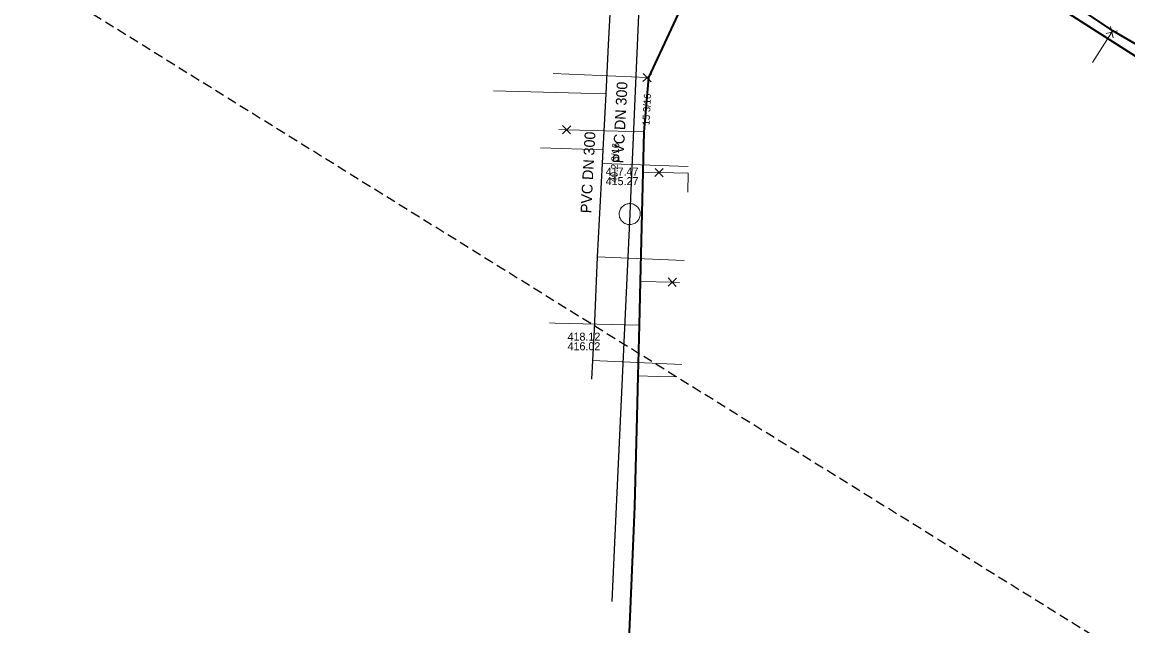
# Model space of a CAD drawing. Extents: x -772952 to -772403, y -1033777 to -1033210.
# Drawn here: x -772951.7 to -772827.4, y -1033657.9 to -1033589.9 of the extents above; entities that cross this region are included whole.
import ezdxf

# ---------------------------------------------------------------- set-up
doc = ezdxf.new("R2010")
doc.units = 0
doc.header["$LTSCALE"] = 0.36
doc.linetypes.add('MEDIUM_DASHED', pattern=[4.5, 3, -1.5])
for name, color, linetype, lineweight in [('15', 7, 'Continuous', 13), ('16', 7, 'Continuous', 35), ('2', 7, 'Continuous', 25), ('4', 7, 'Continuous', 13), ('57', 7, 'Continuous', 13), ('59', 7, 'Continuous', 13), ('62', 7, 'MEDIUM_DASHED', 25)]:
    doc.layers.add(name, color=color, linetype=linetype, lineweight=lineweight)
doc.layers.add('3', color=7, linetype='Continuous')
doc.layers.add('6', color=7, linetype='Continuous')

msp = doc.modelspace()

# ---------------------------------------------------------------- linework, layer by layer
at = {"layer": '15'}
for p, q in [((-772829.321, -1033590.429), (-772829.041, -1033591.701)), ((-772828.553, -1033590.926), (-772829.814, -1033591.2)), ((-772880.951, -1033595.741), (-772881.912, -1033596.62)), ((-772880.997, -1033596.655), (-772881.865, -1033595.701)), ((-772890.015, -1033601.595), (-772890.958, -1033602.492)), ((-772890.042, -1033602.509), (-772890.93, -1033601.573)), ((-772880.561, -1033607.307), (-772879.616, -1033606.41)), ((-772880.532, -1033606.392), (-772879.646, -1033607.33)), ((-772879.078, -1033619.639), (-772878.135, -1033618.742)), ((-772879.051, -1033618.724), (-772878.164, -1033619.662))]:
    msp.add_line(p, q, dxfattribs=at)
at = {"layer": '16'}
for points in [[(-772759.272, -1033597.956), (-772777.938, -1033599.996), (-772804.013, -1033600.436), (-772815.616, -1033598.743), (-772829.081, -1033590.92), (-772839.554, -1033583.848), (-772854.907, -1033577.034), (-772868.037, -1033573.403), (-772870.403, -1033572.723)], [(-772888.497, -1033769.491), (-772888.037, -1033763.55), (-772887.271, -1033741.784), (-772886.864, -1033730.232), (-772886.524, -1033720.537), (-772886.265, -1033713.186), (-772886.123, -1033710.892), (-772885.144, -1033695.171), (-772884.647, -1033687.179), (-772883.979, -1033671.67), (-772883.189, -1033653.357), (-772882.844, -1033645.361), (-772882.811, -1033644.388), (-772882.563, -1033634.359), (-772882.448, -1033629.743), (-772882.307, -1033624.035), (-772882.184, -1033619.103), (-772881.88, -1033606.815), (-772881.767, -1033602.26), (-772881.241, -1033596.171), (-772876.388, -1033585.752), (-772873.983, -1033580.212), (-772872.449, -1033576.679), (-772871.839, -1033575.434)], [(-772871.839, -1033575.434), (-772870.427, -1033576.155), (-772849.008, -1033581.096), (-772841.55, -1033584.107), (-772822.87, -1033596.07), (-772815.517, -1033599.879), (-772800.324, -1033602.374), (-772785.625, -1033603.857), (-772759.69, -1033599.467), (-772726.1, -1033595.877), (-772705.133, -1033594.197), (-772687.467, -1033594.611), (-772649.087, -1033602.85)]]:
    msp.add_lwpolyline(points, dxfattribs=at)
at = {"layer": '2'}
for points in [[(-772885.23, -1033580.92), (-772885.425, -1033584.844), (-772885.564, -1033587.637), (-772885.806, -1033592.497), (-772886.08, -1033597.99), (-772886.395, -1033604.32), (-772886.471, -1033605.845), (-772887.037, -1033616.344), (-772887.401, -1033624.519), (-772887.574, -1033627.991), (-772887.68, -1033630.11)], [(-772882.37, -1033588.25), (-772883.311, -1033609.744), (-772883.39, -1033611.53)], [(-772883.39, -1033611.53), (-772884.21, -1033629.155), (-772885.148, -1033649.309), (-772885.42, -1033655.13)]]:
    msp.add_lwpolyline(points, dxfattribs=at)
at = {"layer": '4'}
msp.add_lwpolyline([(-772882.21, -1033611.53), (-772882.216, -1033611.411), (-772882.234, -1033611.294), (-772882.263, -1033611.178), (-772882.304, -1033611.067), (-772882.356, -1033610.96), (-772882.419, -1033610.859), (-772882.492, -1033610.764), (-772882.573, -1033610.678), (-772882.663, -1033610.6), (-772882.761, -1033610.531), (-772882.864, -1033610.473), (-772882.973, -1033610.426), (-772883.087, -1033610.389), (-772883.203, -1033610.364), (-772883.321, -1033610.352), (-772883.44, -1033610.351), (-772883.559, -1033610.362), (-772883.675, -1033610.385), (-772883.789, -1033610.419), (-772883.899, -1033610.465), (-772884.004, -1033610.522), (-772884.102, -1033610.589), (-772884.193, -1033610.665), (-772884.276, -1033610.75), (-772884.35, -1033610.844), (-772884.414, -1033610.944), (-772884.468, -1033611.05), (-772884.511, -1033611.161), (-772884.543, -1033611.275), (-772884.562, -1033611.393), (-772884.57, -1033611.512), (-772884.566, -1033611.63), (-772884.55, -1033611.748), (-772884.522, -1033611.864), (-772884.483, -1033611.976), (-772884.432, -1033612.084), (-772884.371, -1033612.186), (-772884.3, -1033612.282), (-772884.22, -1033612.369), (-772884.131, -1033612.449), (-772884.035, -1033612.519), (-772883.932, -1033612.579), (-772883.824, -1033612.628), (-772883.711, -1033612.666), (-772883.595, -1033612.692), (-772883.477, -1033612.707), (-772883.358, -1033612.71), (-772883.24, -1033612.701), (-772883.122, -1033612.68), (-772883.008, -1033612.647), (-772882.898, -1033612.603), (-772882.792, -1033612.548), (-772882.693, -1033612.482), (-772882.6, -1033612.407), (-772882.516, -1033612.323), (-772882.441, -1033612.231), (-772882.375, -1033612.132), (-772882.319, -1033612.027), (-772882.275, -1033611.917), (-772882.241, -1033611.803), (-772882.22, -1033611.686), (-772882.21, -1033611.567)], close=True, dxfattribs=at)
at = {"layer": '57'}
for p, q in [((-772886.08, -1033597.99), (-772898.72, -1033597.66)), ((-772886.395, -1033604.32), (-772893.44, -1033604.07)), ((-772886.471, -1033605.845), (-772876.83, -1033606.18)), ((-772887.037, -1033616.344), (-772877.25, -1033616.75)), ((-772887.574, -1033627.991), (-772877.53, -1033628.44))]:
    msp.add_line(p, q, dxfattribs=at)
at = {"layer": '59'}
for points in [[(-772829.082, -1033590.92), (-772829.182, -1033591.064), (-772831.35, -1033594.459)], [(-772881.241, -1033596.172), (-772881.431, -1033596.18), (-772891.987, -1033595.71)], [(-772881.767, -1033602.259), (-772890.486, -1033602.044), (-772891.347, -1033602.023)], [(-772881.88, -1033606.815), (-772880.09, -1033606.86), (-772876.813, -1033606.944), (-772876.84, -1033609.074)], [(-772882.185, -1033619.104), (-772878.608, -1033619.192), (-772877.797, -1033619.213)], [(-772882.307, -1033624.035), (-772891.781, -1033623.8), (-772892.394, -1033623.785)], [(-772882.448, -1033629.744), (-772880.312, -1033629.797), (-772878.097, -1033629.852)]]:
    msp.add_lwpolyline(points, dxfattribs=at)
at = {"layer": '62'}
msp.add_lwpolyline([(-772641.514, -1033776.98), (-772641.529, -1033776.987), (-772951.708, -1033584.106), (-772846.395, -1033249.938), (-772562.451, -1033323.146)], close=True, dxfattribs=at)

# ---------------------------------------------------------------- texts
at = {"layer": '3'}
for s, height, p in [('PVC DN 300', 1.2, (-772884.112, -1033605.841)), ('15 3/16', 0.8, (-772881.174, -1033601.564)), ('PVC DN 300', 1.2, (-772887.724, -1033611.46)), ('40.2 3/16', 0.8, (-772884.798, -1033607.999))]:
    msp.add_text(s, height=height, rotation=87, dxfattribs=at).set_placement(p)
at = {"layer": '6'}
for s, p in [('417.47', (-772886.089, -1033607.199)), ('415.27', (-772886.089, -1033608.276)), ('418.12', (-772890.378, -1033625.777)), ('416.02', (-772890.378, -1033626.854))]:
    msp.add_text(s, height=0.9, dxfattribs=at).set_placement(p)

doc.saveas('drawing.dxf')
